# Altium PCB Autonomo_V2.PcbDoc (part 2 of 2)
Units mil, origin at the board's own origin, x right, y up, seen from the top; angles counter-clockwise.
Board outline 3937.01 x 3937.01 mil, 4 copper layers (Top Layer, GND, PWR, Bottom Layer), stack 62.204 mil thick; 148 components, 84 nets, 484 pads, 385 vias.
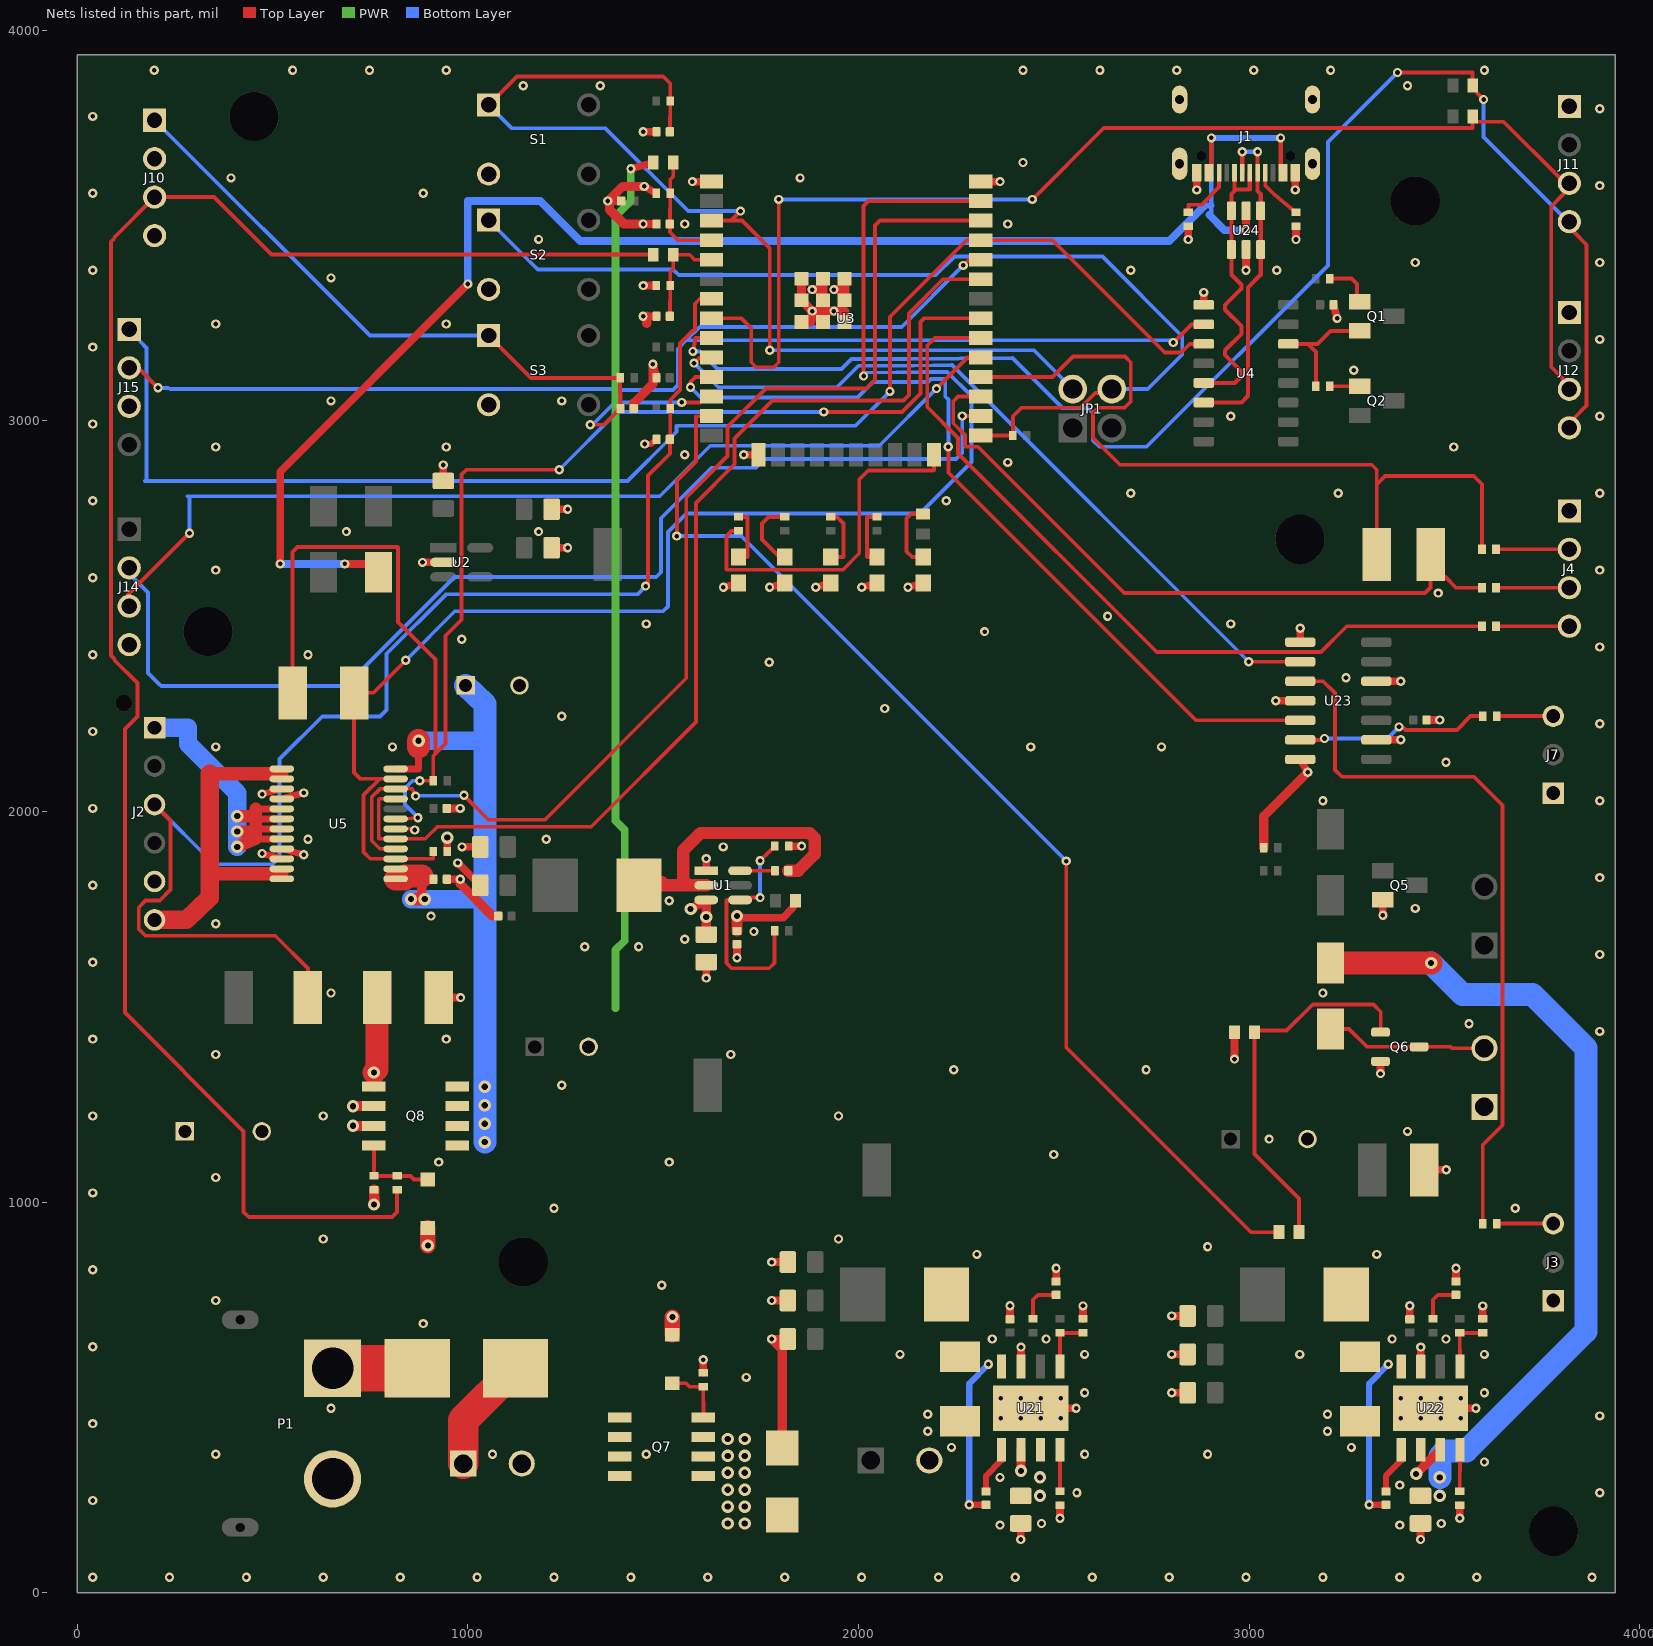
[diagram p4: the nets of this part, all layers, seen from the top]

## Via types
v1: diameter 23.62, hole 11.81, Top Layer to Bottom Layer, tented both sides, 334 vias
v2: diameter 31.5, hole 15.75, Top Layer to Bottom Layer, tented both sides, 51 vias

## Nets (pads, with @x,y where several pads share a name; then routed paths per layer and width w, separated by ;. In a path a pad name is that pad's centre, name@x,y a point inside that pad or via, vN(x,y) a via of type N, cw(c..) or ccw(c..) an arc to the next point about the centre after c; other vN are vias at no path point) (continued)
ENC_B: C18.1 J2.3 R15.2 TP4.1 U3.7 | length 3611.9
  Top Layer w9.84: J2.3@197.83,2017.72 239,1976.55 239,1800 211,1772 175,1772 157.48,1754.48 157.48,1699.61 175,1682.08 506.92,1682.08 590.55,1598.45 TP4.1@590.55,1523.62 ; v1(1455,2577) 1461,2583 1461,2860 1517.01,2916.01 C18.1@1517.01,2952.76 1518.21,2952.76 1518.21,2967.52 1517.91,2967.82 R15.2@1517.91,3031.5 1517.91,3053.91 1543,3079 1543,3198 1575,3230 1577,3230 1581,3234 1581,3300 1593.6,3312.6 U3.7@1624.02,3312.6
  Bottom Layer w9.84: J2.3@197.83,2017.72 350.55,1865 500,1865 518,1883 518,2134 627,2243 775,2243 792.04,2260.04 792.04,2403.77 944.27,2556 1434,2556 v1(1455,2577)
ESP_EN: C12.1 JP1.2 R6.2 S1.1 U3.3 | length 2674.4
  Top Layer w9.84: S1.1@1053.15,3809.06 1126.09,3882 1500,3882 1517.91,3864.09 R6.2@1517.91,3818.9 1517.91,3779.91 1517.01,3779 C12.1@1517.01,3740.16 ; U3.3@1624.02,3512.6 1673.6,3512.6 ; v1(1698,3537) 1673.6,3512.6 ; v1(1773,3181) 1773,3441.6 1702,3512.6 1673.6,3512.6
  Bottom Layer w9.84: S1.1@1053.15,3809.06 1113.21,3749 1352,3749 1564,3537 v1(1698,3537) ; v1(1773,3181) 2448.92,3181 JP1.2@2548.43,3081.5
ESP_RX: J15.2 U3.34 U4.2 | length 3704.7
  Top Layer w9.84: J15.2@161.42,3129.92 v1(206.69,3084.65) ; v1(2268,3398) 2282.6,3412.6 U3.34@2312.99,3412.6 ; v1(2806,3200.64) 2852.41,3247.05 U4.2@2883.86,3247.05
  Bottom Layer w9.84: v1(206.69,3084.65) 232.28,3084.65 ; 238.3,3082 1391,3082 1394,3079 1525,3079 1537.5,3091.5 1537.5,3184.78 1559.14,3206.41 ; v1(2268,3398) 2110.75,3240.75 1593.47,3240.75 1559.14,3206.41 ; v1(2806,3200.64) 2800.23,3206.41 1559.14,3206.41
ESP_TX: J15.1 U3.35 U4.3 | length 3574
  Top Layer w9.84: v1(2080.5,3075.5) 2080.5,3266.49 2276.6,3462.6 U3.35@2312.99,3462.6 2496.35,3462.6 2783.95,3175 2825.95,3175 2848,3197.05 U4.3@2883.86,3197.05
  Bottom Layer w9.84: 161.42,3202.76 177.17,3187.01 177.17,2850.39 ; 173.39,2845.9 1408.31,2845.9 1521.86,2959.45 1534.5,2972.09 1534.5,2987.64 1992.64,2987.64 v1(2080.5,3075.5)
ESTOP_G: J10.3 R42.2 R43.1 | length 4595.9
  Top Layer w9.84: 92.52,3464.57 86.61,3458.66 86.61,2399.61 94.49,2391.73 ; 96,2387 154,2329 154,2243 122,2211 122,1485 426,1181 426,975 439,962 805.9,962 818.9,975 R42.2@818.9,1031.3 ; 96,3471 J10.3@197.83,3572.83 350.17,3572.83 497,3426 1474.41,3426 R43.1@1474.41,3425.2
ESTOP_SENSE: C38.1 R43.2 R44.1 U3.5 | length 264.7
  Top Layer w9.84: C38.1@1517.01,3267.72 1517.01,3306 1517.91,3306.91 R44.1@1517.91,3346.46 1517.91,3381 1525.59,3388.68 R43.2@1525.59,3425.2 1568,3425.2 1580.6,3412.6 U3.5@1624.02,3412.6
EXP_IO4: J14.2 U3.26 | length 2819.4
  Top Layer w9.84: v1(2265.63,3012.6) U3.26@2312.99,3012.6
  Bottom Layer w9.84: 145.67,2596.46 181.1,2561.02 181.1,2354.33 210.63,2324.8 ; 215,2321 687,2321 966,2600 1482.14,2600 1494.64,2612.5 1494.64,2750.64 1624,2880 1738.21,2880 1760.45,2902.24 2250,2902.24 2265.63,2917.87 v1(2265.63,3012.6)
EXP_IO5: J14.3 U3.29 | length 2489.3
  Top Layer w9.84: 129.92,2555.12 v1(287.4,2712.6) ; v1(2199.59,3082.68) 2279.5,3162.6 U3.29@2312.99,3162.6
  Bottom Layer w9.84: 282.27,2806.98 1491.25,2806.98 1620.54,2936.27 2053.17,2936.27 v1(2199.59,3082.68) ; v1(287.4,2712.6) 287.4,2801.18
FB_SERVO: R23.2 R24.1 U22.5 | length 145.6
  Top Layer w9.84: U22.5@3539.57,578.74 3539.57,621 3539.37,621.2 R23.2@3539.37,665.16 R24.1@3598.43,665.16
FB_VJET: R19.2 R20.1 U21.5 | length 145.6
  Top Layer w9.84: U21.5@2515.94,578.74 2515.94,621 2515.75,621.2 R19.2@2515.75,665.16 R20.1@2574.8,665.16
GND: C1.N C2.2 C3.2 C4.2 C6.2 C7.2 C8.2 C9.2 C10.2 C11.2 C12.2 C13.2 C14.N C15.2 C16.2 C17.2 C18.2 C19.N C20.2 C21.N C22.2 C23.2 C24.2 C26.2 C27.2 C28.2 C29.2 C30.2 C31.2 C32.2 C34.2 C35.2 C36.2 C37.2 C38.2 D3.A D4.A D5.1 D6.1 D7.1 D8.1 D9.1 D12.A J1.A1_B12 J1.B1_A12 J1.SH1 J1.SH2 J1.SH3 J1.SH4 J2.5 J3.1 J4.1 J5.2 J7.1 J10.2 J10.4 J11.1 J12.1 J14.4 J15.3 P1.2 Q5.2 Q6.2 R2.2 R5.2 R8.2 R9.2 R12.2 R20.2 R21.2 R24.2 R25.2 R34.2 R36.2 R44.2 R45.2 S1.3 S2.3 S3.3 TP12.1 TP13.1 U1.1 U2.2 U3.1 U3.15 U3.38 U3.39 U4.1 U5.3 U5.4 U5.9 U5.10 U5.18 U21.7 U21.9 U22.7 U22.9 U23.1 U23.4 U23.7 U23.9 U23.12 U24.2 | length 4710.2
  Top Layer w9.84: U5.18@838.58,1955.71 850.39,1955.71 v1(864.17,1952.76)
  Top Layer w15.75: v1(1452.76,2940.94) 1468.5,2940.94 C18.2@1482.99,2952.76
  Top Layer w17.72: v1(473.11,1892.48) U5.10@523.62,1878.94 ; v1(473.11,2044.53) U5.3@523.62,2058.07 ; U5.9@523.62,1904.53 v1(579.84,1889.45) ; U5.4@523.62,2032.48 v1(579.84,2047.56)
  Top Layer w19.68: v1(883.7,2637.8) U2.2@936.99,2637.8 ; TP12.1@925.2,1523.62 v1(981.3,1523.62) ; C8.2@937.01,2846.26 v1(937.01,2887.2) ; C15.2@946.14,1826.77 v1(980.47,1826.77) ; C16.2@946.14,2007.87 v1(980.47,2007.87) ; R12.2@947.05,1897.64 v2(947.05,1933.15) ; v1(974.25,1868.46) C6.2@1031.69,1811.02 ; v1(984.84,1909.45) C7.2@1031.69,1909.45 ; C9.2@1214.37,2675.2 v1(1255.32,2675.2) ; C10.2@1214.37,2773.62 v1(1255.32,2773.62) ; v1(1358.11,3562.99) C11.2@1392.44,3562.99 ; v1(1448.66,3267.72) 1458.15,3267.72 C38.2@1482.99,3267.72 ; v1(1448.66,3503.94) C2.2@1482.99,3503.94 ; v1(1448.66,3740.16) C12.2@1482.99,3740.16 ; v1(1448.74,3346.46) R44.2@1482.09,3346.46 ; v1(1451.38,3600.39) R2.2@1482.09,3582.68 ; v1(1473.66,3145.08) C17.2@1482.99,3110.24 ; v1(1574.8,3612.6) U3.1@1624.02,3612.6 ; R45.2@1602.36,563.19 v1(1602.36,596.54) ; v1(1610.24,1573.43) C3.2@1610.24,1614.37 ; U1.1@1610.22,1848.43 v1(1610.24,1879.37) ; v1(1654.21,2574.29) D5.1@1692.91,2584.65 ; v1(1688.98,1625.83) C4.2@1688.98,1660.16 ; v1(1706.3,2913.39) U3.15@1743.7,2913.39 ; v1(1772.32,2574.29) D6.1@1811.02,2584.65 ; v1(1778.15,649.61) C22.2@1819.09,649.61 ; v1(1778.15,748.03) C23.2@1819.09,748.03 ; v1(1778.15,846.46) C28.2@1819.09,846.46 ; R5.2@1821.06,1911.42 v1(1854.41,1911.42) ; v1(1890.43,2574.29) D7.1@1929.13,2584.65 ; v1(2008.54,2574.29) D8.1@2047.24,2584.65 ; v1(2126.65,2574.29) D9.1@2165.35,2584.65 ; U3.38@2312.99,3612.6 v1(2362.2,3612.6) ; C27.2@2387.8,700.08 v1(2387.8,734.41) ; v1(2415.35,136.42) C24.2@2415.35,177.36 ; U21.7@2415.94,578.74 v1(2415.94,628.94) ; U21.9@2440.94,472.44 v1(2557.09,472.44) ; C26.2@2505.91,796.54 v1(2505.91,830.87) ; v1(2515.75,190.87) R21.2@2515.75,224.21 ; R20.2@2574.8,700.98 v1(2574.8,734.33) ; v1(2801.77,511.81) C31.2@2842.72,511.81 ; v1(2801.77,610.24) C29.2@2842.72,610.24 ; v1(2801.77,708.66) C30.2@2842.72,708.66 ; v1(2844.49,3464.49) R9.2@2844.49,3497.83 ; v1(2866.14,3591.34) J1.B1_A12@2866.14,3635.63 ; U4.1@2883.86,3297.05 v1(2883.86,3328.94) ; v1(2962.6,1366.14) R36.2@2962.6,1435.04 ; v1(2992.13,3385.83) U24.2@2992.13,3438.78 ; v1(3068.43,2283.46) U23.4@3130.91,2283.46 ; v1(3118.11,3591.34) J1.A1_B12@3118.11,3635.63 ; v1(3120.08,3464.49) R8.2@3120.08,3497.83 ; U23.7@3130.91,2133.46 v1(3149.88,2100.59) ; U23.1@3130.91,2433.46 v1(3130.91,2468.98) ; C13.2@3215.83,3297.24 v1(3225.16,3262.4) ; U23.9@3325.79,2183.46 v1(3388.27,2183.46) ; U23.12@3325.79,2333.46 v1(3388.27,2333.46) ; v1(3336.42,1328.94) Q6.2@3336.42,1360.24 ; v1(3342.52,1734.25) Q5.2@3342.52,1773.62 ; C35.2@3411.42,700.08 v1(3411.42,734.41) ; v1(3438.98,136.42) C32.2@3438.98,177.36 ; U22.7@3439.57,578.74 v1(3439.57,628.94) ; TP13.1@3448.82,1082.68 v1(3504.92,1082.68) ; C36.2@3454.02,2234.25 v1(3488.35,2234.25) ; U22.9@3464.57,472.44 v1(3580.71,472.44) ; C34.2@3529.53,796.54 v1(3529.53,830.87) ; v1(3539.37,190.87) R25.2@3539.37,224.21 ; R24.2@3598.43,700.98 v1(3598.43,734.33)
  Top Layer w23.62: v1(980.47,1826.77) 980.47,1814.81 1063,1732.28 C20.2@1077.48,1732.28 ; C37.2@1424.49,3031.5 1424.49,3045.49 1473.66,3094.66 v1(1473.66,3145.08) ; v1(1448.66,3503.94) 1399.67,3503.94 1362.5,3541.11 1362.5,3566.11 1396.79,3600.39 v1(1451.38,3600.39) ; 1458.15,3250 1458.15,3267.72 v1@1458.15,3268.54 ; v1(1778.15,649.61) 1805,622.76 D12.A@1805,370 ; U3.39@1854.33,3253.54 1878,3253.54 1878.61,3257.9 v1(1881.89,3281.1) ; U3.39@1854.33,3363.78 U3.39@1854.33,3308.66 v1(1881.89,3281.1) ; v1(1881.89,3336.22) 1908,3336.22 ; U3.39@1909.45,3253.54 v1(1881.89,3281.1) ; U3.39@1909.45,3308.66 1909.45,3335 1908.23,3336.22 1908,3336.22 ; U3.39@1909.45,3363.78 1909.45,3337.67 1908,3336.22 ; v1(1937.01,3336.22) 1963,3336.22 ; U3.39@1964.57,3253.54 1964.57,3280 1963.46,3281.1 v1(1937.01,3281.1) v1(1881.89,3281.1) ; U3.39@1964.57,3308.66 1964.57,3335 1963.35,3336.22 1963,3336.22 ; U3.39@1964.57,3363.78 1964.57,3337.79 1963,3336.22 ; R34.2@3037.2,1907.48 3037.2,1987.91 v1(3149.88,2100.59)
  other v1: 39.37,39.37 236.22,39.37 433.07,39.37 629.92,39.37 826.77,39.37 1023.62,39.37 1220.47,39.37 1417.32,39.37 1614.17,39.37 1811.02,39.37 2007.87,39.37 2204.72,39.37 2401.57,39.37 2598.43,39.37 2795.28,39.37 2992.13,39.37 3188.98,39.37 3385.83,39.37 3582.68,39.37 3877.95,39.37 2362.2,173.23 3385.83,173.23 2468.5,177.17 3492.13,177.17 39.37,236.22 2559.06,255.91 3897.64,255.91 3385.83,275.59 2362.2,295.28 3602.36,334.65 354.33,354.33 1062.99,354.33 1456.69,354.33 2578.74,354.33 2893.7,354.33 2238.19,372.05 3261.81,372.05 2177.17,413.39 3200.79,413.39 39.37,433.07 3897.64,452.76 2177.17,456.69 3200.79,456.69 649.61,472.44 2578.74,511.81 3602.36,511.81 1712.6,551.18 2106.3,610.24 2578.74,610.24 3129.92,610.24 3602.36,610.24 39.37,629.92 2342.52,649.61 2480.32,649.61 3366.14,649.61 3503.94,649.61 885.83,688.98 354.33,748.03 1496.06,787.4 39.37,826.77 2303.15,866.14 3326.77,866.14 2893.7,885.83 629.92,905.51 1948.82,905.51 1220.47,984.25 3681.1,984.25 39.37,1023.62 354.33,1062.99 925.2,1102.36 1515.75,1102.36 2500,1122.05 3051.18,1161.42 3405.51,1181.1 39.37,1220.47 629.92,1220.47 1948.82,1220.47 1240.16,1299.21 2244.09,1338.58 2736.22,1338.58 354.33,1377.95 1673.23,1377.95 39.37,1417.32 944.88,1417.32 3897.64,1437.01 3562.99,1456.69 649.61,1535.43 3188.98,1535.43 39.37,1614.17 3897.64,1633.86 1299.21,1653.54 1437.01,1653.54 1555.12,1673.23 1732.28,1692.91 354.33,1712.6 905.51,1732.28 3425.2,1751.97 1515.75,1771.65 39.37,1811.02 3897.64,1830.71 1653.54,1909.45 590.55,1929.13 1200.79,1929.13 39.37,2007.87 3188.98,2027.56 3897.64,2027.56 3503.94,2125.98 354.33,2165.35 807.09,2165.35 2440.94,2165.35 2775.59,2165.35 39.37,2204.72 3897.64,2224.41 1240.16,2244.09 2066.93,2263.78 3248.03,2342.52 1771.65,2381.89 39.37,2401.57 590.55,2401.57 3897.64,2421.26 984.25,2440.94 2322.83,2460.63 1456.69,2480.32 2952.76,2480.32 2637.8,2500 3484.25,2559.06 39.37,2598.43 354.33,2618.11 3897.64,2618.11 688.98,2716.54 1181.1,2716.54 39.37,2795.28 2224.41,2795.28 2696.85,2814.96 3228.35,2814.96 3897.64,2814.96 2381.89,2893.7 1555.12,2913.39 354.33,2933.07 944.88,2933.07 3523.62,2933.07 39.37,2992.13 2952.76,3011.81 3897.64,3011.81 649.61,3051.18 1240.16,3051.18 3267.72,3129.92 39.37,3188.98 3897.64,3208.66 354.33,3248.03 944.88,3248.03 649.61,3366.14 39.37,3385.83 2696.85,3385.83 3070.87,3385.83 3425.2,3405.51 3897.64,3405.51 1181.1,3464.57 1555.12,3503.94 2381.89,3503.94 39.37,3582.68 885.83,3582.68 3897.64,3602.36 393.7,3622.05 1850.39,3622.05 2421.26,3661.42 39.37,3779.53 3897.64,3799.21 1141.73,3858.27 1338.58,3858.27 3405.51,3858.27 196.85,3897.64 551.18,3897.64 748.03,3897.64 944.88,3897.64 2421.26,3897.64 2618.11,3897.64 2814.96,3897.64 3011.81,3897.64 3208.66,3897.64 3602.36,3897.64
I2C_SCL: J11.4 J12.4 R39.2 U3.9 | length 3749.8
  Top Layer w9.84: v1(1576,3178) 1583,3212.6 U3.9@1624.02,3212.6 ; v1(3380,3892) 3571.83,3892 R39.2@3572.83,3858.27 ; 3584.65,3838.58 v1(3600.39,3822.83) ; J12.4@3832.68,3007.87 3864.17,3039.37 3864.17,3450.79 3832.68,3482.28
  Bottom Layer w9.84: v1(1576,3178) 1594,3178 1639,3133 1956.54,3133 1982.42,3158.87 2123.18,3158.87 2394.19,3160.81 2522,3033 2587.5,3033 2600.69,3019.81 2600.69,2950 2616.93,2933.76 2737.76,2933.76 3202,3398 3202,3714 v1(3380,3892) ; v1(3600.39,3822.83) 3600.39,3726.38 3797.24,3529.53
I2C_SDA: J11.3 J12.3 R38.2 U3.8 | length 3346.3
  Top Layer w9.84: U3.8@1624.02,3262.6 1700.4,3262.6 1725.5,3237.5 1725.5,3150 1738,3137.5 1783.5,3137.5 1796,3150 v1(1796,3567) ; v1(2445,3567) 2628,3750 3571.83,3750 R38.2@3572.83,3779.53 ; R38.2@3584.65,3765.75 3651.57,3765.75 3793.31,3624.02 ; J12.3@3805.12,3106.3 3773.62,3137.8 3773.62,3549.21 3805.12,3580.71
  Bottom Layer w9.84: v1(1796,3567) v1(2445,3567)
IO0: JP1.4 R7.2 S2.1 U3.25 | length 2621.3
  Top Layer w9.84: U3.25@2312.99,2962.6 R7.2@2395.47,2962.6 2395.47,3012 2417.23,3033.76 2568.2,3033.76 2606,3071.56 2648.43,3071.56 JP1.4@2648.43,3081.5
  Bottom Layer w9.84: S2.1@1053.15,3513.78 1178.93,3388 1524.97,3388 1539.91,3373.06 2197.78,3373.06 2245.36,3420.64 2624.36,3420.64 2829,3216 2829,3170 2740.5,3081.5 JP1.4@2648.43,3081.5
J4_HB: J4.4 R40.1 | length 187.8
  Top Layer w9.84: R40.1@3632.09,2474.41 J4.4@3819.88,2474.41
J4_RX: J4.3 R18.1 | length 187.8
  Top Layer w9.84: R18.1@3632.09,2572.83 J4.3@3819.88,2572.83
J4_TX: J4.2 R17.1 | length 187.8
  Top Layer w9.84: R17.1@3632.09,2671.26 J4.2@3819.88,2671.26
JETSON_HB: R40.2 U3.30 | length 2033.5
  Top Layer w9.84: U3.30@2312.99,3212.6 2195.95,3212.6 2176.07,3192.72 2176.07,3035.35 2254.92,2956.51 2254.92,2916.6 2763.51,2408 3183.59,2408 3250,2474.41 R40.2@3596.26,2474.41
LED_3V3_A: D6.2 R29.2 | length 182.5
  Top Layer w9.84: D6.2@1811.02,2651.57 1798,2651.57 1753,2696.57 1753,2737.5 1769.63,2754.13 R29.2@1811.02,2754.13
LED_5V_A: D7.2 R30.2 | length 158
  Top Layer w9.84: D7.2@1929.13,2651.57 1961,2651.57 1962,2652.57 1962,2737.5 1945.37,2754.13 R30.2@1929.13,2754.13
LED_DATA_3V3: U3.11 U23.5 | length 2162.4
  Top Layer w9.84: v1(1570,3086) 1570,3100 1582.6,3112.6 U3.11@1624.02,3112.6 ; v1(2230,2934) 2230,2867.09 2863.63,2233.46 U23.5@3130.91,2233.46
  Bottom Layer w9.84: v1(1570,3086) 1596,3060 1997,3060 2037,3100 2178,3100 2185.66,3107.66 2221,3107.66 2222.22,3106.44 2222.22,3062.5 2230,3054.72 v1(2230,2934)
LED_DATA_5V: R27.1 U23.6 | length 493.9
  Top Layer w9.84: U23.6@3130.91,2183.46 v1@3190.46,2183.46 ; v1@3387,2222 3400,2209 3532,2209 3567.09,2244.09 R27.1@3598.23,2244.09
  Bottom Layer w9.84: v1(3192.91,2187.01) 3354.33,2187.01 v1(3383.86,2216.54)
LED_DIN: J7.3 R27.2 | length 144.5
  Top Layer w9.84: R27.2@3634.06,2244.09 J7.3@3778.54,2244.09
LED_HB: R28.1 U3.24 | length 909.4
  Top Layer w9.84: R28.1@1692.91,2718.31 1675,2718.31 1662,2705.31 1662,2620 1663,2619 1960,2619 2002,2661 2002,2850 2025,2873 2192.7,2873 2193.7,2874 U3.24@2193.7,2913.39
LED_HB_A: D5.2 R28.2 | length 147.6
  Top Layer w9.84: D5.2@1692.91,2651.57 1715,2651.57 1716,2652.57 1716,2753.13 1715,2754.13 R28.2@1692.91,2754.13
LED_SRV_A: D8.2 R31.2 | length 151.9
  Top Layer w9.84: D8.2@2047.24,2651.57 2023,2651.57 2022,2652.57 2022,2753.13 2023,2754.13 R31.2@2047.24,2754.13
LED_VJET_A: D9.2 R32.2 | length 179.4
  Top Layer w9.84: D9.2@2165.35,2651.57 2137.5,2651.57 2123.03,2666.04 2123.03,2749.84 2135,2761.81 R32.2@2165.35,2761.81
LIGHT_G: Q6.1 R35.2 R36.1 | length 974.7
  Top Layer w9.84: R35.2@3127.95,923.23 3127.95,1009 3013.78,1123.17 R36.1@3013.78,1435.04 3013.78,1439 3096,1439 3163,1506 3318.5,1506 3337,1487.5 3337,1435.04 Q6.1@3336.42,1435.04
LIGHT_N: D11.1 J9.2 Q6.3 | length 414
  Top Layer w9.84: D11.1@3208.66,1442.91 3256.09,1442.91 3301.36,1397.64 Q6.3@3435.24,1397.64 3516,1397.64 3519.74,1393.9 J9.2@3602.36,1393.9
LIGHTS: R35.1 U3.13 | length 2926.6
  Top Layer w9.84: v1(1535,2705) 1535,2847.34 1583.66,2896 1583.66,3011.26 U3.13@1624.02,3012.6 ; v1(2532,1873) 2532,1395.5 3004.5,923 3076.77,923 R35.1@3076.77,923.23
  Bottom Layer w9.84: v1(1535,2705) 1700,2705 v1(2532,1873)
MOT_A: J2.6 U5.1 U5.2 U5.11 U5.12 | length 850.8
  Top Layer w35.43: 338.58,1840.55 523.62,1840.55 ; 338.58,2096.46 523.62,2096.46
  Top Layer w47.24: J2.6@197.83,1722.44 279.53,1722.44 338.58,1779.53 338.58,1840.55 338.58,2096.46
MOT_B: J2.1 U5.5 U5.6 U5.7 U5.8 | length 933.5
  Top Layer w17.72: 456.69,1930.12 U5.8@523.62,1930.12 ; 456.69,1955.71 U5.7@523.62,1955.71 ; 456.69,1981.3 U5.6@523.62,1981.3 ; 456.69,2006.89 U5.5@523.62,2006.89
  Top Layer w31.5: v2(409.45,1909.45) 456.69,1930.12 456.69,1948.82 ; v2(409.45,1948.82) 456.69,1948.82 ; v2(409.45,1988.19) 456.69,1988.19 ; 456.69,2006.89 456.69,1988.19 ; 456.69,1948.82 456.69,1955.71 456.69,1981.3 456.69,1988.19
  Bottom Layer w47.24: J2.1@197.83,2214.57 283.46,2214.57 283.46,2173.23 409.45,2047.24 v2(409.45,1988.19) v2(409.45,1948.82) v2(409.45,1909.45)
MOT_IN1: U3.33 U5.17 U5.21 | length 2768.2
  Top Layer w9.84: U5.21@814.96,2032.48 773,2032.48 772,2031.48 772,1931.12 773,1930.12 799.8,1930.12 U5.17@814.96,1930.12 891,1930.12 921.88,1961 1316,1961 1584,2229 1584,2790 1683,2889 1683,2955 1780,3052 2115,3052 2129,3066 2129,3275 2216.6,3362.6 U3.33@2312.99,3362.6
MOT_IN2: U3.36 U5.16 U5.22 | length 2968.7
  Top Layer w9.84: U5.16@814.96,1904.53 774.47,1904.53 754,1925 754,2037.5 774.57,2058.07 U5.22@814.96,2058.07 857,2058.07 v1(866.14,2039.37) ; v1(990.16,2041.34) 1052.48,1979.02 1197.01,1979.02 1559,2341 1559,2804 1665,2910 1665,2985 1763,3083 2020,3083 2042,3105 2042,3500 2054.6,3512.6 U3.36@2312.99,3512.6
  Bottom Layer w9.84: v1(866.14,2039.37) v1(990.16,2041.34)
MOT_PWM: R12.1 TP2.1 U3.37 U5.15 U5.23 | length 3875.7
  Top Layer w9.84: U5.23@814.96,2083.66 774.33,2083.66 ; v1(841,2387) 758,2304 708.66,2304 TP2.1@708.66,2303.15 708.66,2100 725,2083.66 774.33,2083.66 ; R12.1@911.22,1897.64 911.22,1880 910.16,1878.94 U5.15@814.96,1878.94 750,1878.94 733,1895.94 733,2042.33 774.33,2083.66 ; v1(2013,3115) 2013,3550 2025.6,3562.6 U3.37@2312.99,3562.6
  Bottom Layer w9.84: v1(841,2387) 966.5,2512.5 1499.86,2512.5 1512.36,2525 1512.36,2715.36 1560,2763 2157,2763 2289,2895 2289,3063.44 2227.06,3125.38 2168.11,3125.38 2021.44,3123.44 v1(2013,3115)
MOT_STBY: R13.2 TP1.1 U3.31 U5.19 | length 3847.3
  Top Layer w9.84: TP1.1@551.18,2303.15 551.18,2664.18 564,2677 820,2677 821,2676 821,2485 917,2389 917,2147.78 ; U5.19@814.96,1981.3 846.46,1981.3 v1(872.05,1984.25) ; v1(877,2078.74) R13.2@911.22,2078.74 911.22,2142 917,2147.78 ; v1(1234,2875) 996.5,2875 984,2862.5 984,2491 943,2450 943,2173.78 917,2147.78 ; v1(1911,3023) 2111.3,3023 2158.36,3070.06 2158.36,3253.36 2167.6,3262.6 U3.31@2312.99,3262.6
  Bottom Layer w9.84: v1(872.05,1984.25) 838.58,2017.72 838.58,2059.06 858.27,2078.74 v1(877,2078.74) ; v1(1234,2875) 1382,3023 v1(1911,3023)
NetC25_1: C25.1 U21.1 | length 123.2
  Top Layer w15.75: C25.1@2326.77,259.13 2326.77,299.21 2365.94,338.58 U21.1@2365.94,366.14
NetC33_1: C33.1 U22.1 | length 123.2
  Top Layer w15.75: C33.1@3350.39,259.13 3350.39,299.21 3389.57,338.58 U22.1@3389.57,366.14
NetF1_1: F1.1 P1.1 | length 217
  Top Layer w118.11: P1.1@653.54,574.8 F1.1@870.56,574.8
NetF1_2: F1.2 P2.1 | length 299.3
  Top Layer w78.74: P2.1@987.99,330.71 987.99,440.94 F1.2@1121.56,574.8
NetJ1_A5: J1.A5 R8.1 | length 137.9
  Top Layer w9.84: J1.A5@3041.34,3635.63 3041.34,3602.36 3062.99,3580.71 R8.1@3120.08,3533.66
NetJ1_B5: J1.B5 R9.1 | length 154.2
  Top Layer w9.84: R9.1@2844.49,3533.66 2844.49,3553.15 2877.95,3553.15 2923.23,3598.43 J1.B5@2923.23,3635.63
NetJ3_3: J3.3 R16.1 | length 144.5
  Top Layer w9.84: R16.1@3634.06,944.88 J3.3@3778.54,944.88
NetQ1_1: Q1.1 R10.2 | length 127.7
  Top Layer w9.84: R10.2@3206.89,3364.17 3262.5,3364.17 3276,3350.67 3276,3305.12 Q1.1@3283.46,3305.12
NetQ2_1: Q2.1 R11.2 | length 76.6
  Top Layer w9.84: R11.2@3206.89,3088.58 Q2.1@3283.46,3088.58
Q7_G: D13.2 Q7.4 R45.1 | length 161
  Top Layer w9.84: D13.2@1523.62,536.42 1558,536.42 1567.06,527.36 R45.1@1602.36,527.36 1602.36,487.47 1602.83,487 Q7.4@1602.83,449.02
Q8_G: D14.2 Q8.4 R41.2 R42.1 | length 220.1
  Top Layer w9.84: Q8.4@759.37,1145.47 759.37,1106.47 759.84,1106 R41.2@759.84,1067.13 R42.1@818.9,1067.13 853,1067.13 862.06,1058.07 D14.2@897.64,1058.07
RC_SERVO: C34.1 R26.2 | length 113.3
  Top Layer w9.84: R26.2@3470.47,700.98 3470.47,750 3482.99,762.52 C34.1@3529.53,762.52
RC_VJET: C26.1 R22.2 | length 113.3
  Top Layer w9.84: R22.2@2446.85,700.98 2446.85,750 2459.37,762.52 C26.1@2505.91,762.52
RT_SERVO: R25.1 U22.4 | length 106.2
  Top Layer w9.84: R25.1@3539.37,260.04 3539.37,312 3539.57,312.2 U22.4@3539.57,366.14
RT_VJET: R21.1 U21.4 | length 106.2
  Top Layer w9.84: R21.1@2515.75,260.04 2515.75,312 2515.94,312.2 U21.4@2515.94,366.14
RTS: Q1.2 R11.1 U4.14 | length 314
  Top Layer w9.84: U4.14@3100.39,3197.05 3150,3197.05 ; R11.1@3171.06,3088.58 3171.06,3175.98 3150,3197.05 ; Q1.2@3283.46,3230.32 3208.27,3230.32 3175,3197.05 3150,3197.05
SERVO: R16.2 U23.3 | length 1856.8
  Top Layer w9.84: U23.3@3130.91,2333.46 3189.54,2333.46 3220,2303 3220,2106.5 3237.5,2089 3576,2089 3649,2016 3649,1196.77 3598.23,1146 R16.2@3598.23,944.88
SERVO_3V3: U3.10 U23.2 | length 1966.2
  Top Layer w9.84: v1(1579,3148) 1593.6,3162.6 U3.10@1624.02,3162.6 ; v1(2999.2,2383.46) U23.2@3130.91,2383.46
  Bottom Layer w9.84: v1(1579,3148) 1641,3086 1944.85,3086 2000,3141.15 2140.89,3141.15 2239.56,3143.1 v1(2999.2,2383.46)
START_BTN: C37.1 J10.1 R37.2 S3.1 U3.12 | length 1976.8
  Top Layer w9.84: S3.1@1053.15,3218.5 1161.42,3110.24 R37.2@1389.57,3110.24 1389.57,3070.91 1390.47,3070 C37.1@1390.47,3031.5 1377.95,3019.68 1348.43,2990.16 v1(1312.99,2990.16) ; v1(1547.24,3047.24) 1594.49,3047.24 U3.12@1624.02,3062.6
  Bottom Layer w9.84: J10.1@197.83,3769.69 749.02,3218.5 S3.1@1053.15,3218.5 ; v1(1312.99,2990.16) 1318.9,2990.16 1375.98,3047.24 v1(1547.24,3047.24)
SW: C5.2 L1.1 U1.2 | length 770.2
  Top Layer w31.5: L1.1@1437.99,1811.02 1437.99,1819 1496.06,1819 1496.06,1811.02 1564.98,1811.02 ; U1.2@1610.22,1811.02 1564.98,1811.02 ; C5.2@1820.16,1848.43 1845.43,1848.43 1887.88,1890.88 1887.88,1932.01 1875,1944.88 1595.88,1944.88 1551,1900 1551,1825 1564.98,1811.02
SW_SERVO: C33.2 D4.C L3.1 U22.8 | length 423.2
  Top Layer w15.75: v1(3307.09,225.12) C33.2@3350.39,225.12
  Bottom Layer w15.75: v1(3307.09,225.12) 3307.09,535.43 v1(3356.3,584.65)
SW_VJET: C25.2 D3.C L2.1 U21.8 | length 423.2
  Top Layer w15.75: v1(2283.46,225.12) C25.2@2326.77,225.12
  Bottom Layer w15.75: v1(2283.46,225.12) 2283.46,535.43 v1(2332.68,584.65)
UART2_RX: R18.2 TP6.1 U3.27 | length 1783.7
  Top Layer w9.84: U3.27@2312.99,3062.6 2255.14,3062.6 2242.54,3050 2242.54,2993.94 2272.64,2963.85 2272.64,2935 2273.64,2934 2305.25,2934 2680.25,2559 3450,2559 3464.57,2573.57 TP6.1@3464.57,2600 ; TP6.1@3464.57,2657.48 TP6.1@3464.57,2600 ; R18.2@3596.26,2572.83 3530,2572.83 3502.83,2600 TP6.1@3464.57,2600
UART2_TX: R17.2 TP5.1 U3.28 | length 2117
  Top Layer w9.84: U3.28@2312.99,3112.6 2496.6,3112.6 2549,3165 2682,3165 2697,3150 2697,3050 2680.76,3033.76 2612.5,3033.76 2600,3021.26 2600,2957 2669.22,2887.78 3313.99,2887.78 3326.77,2875 3326.77,2837.5 ; TP5.1@3326.77,2657.48 3326.77,2837.5 ; R17.2@3596.26,2671.26 3596.26,2837.74 3575,2859 3348.27,2859 3326.77,2837.5
USB_DN: J1.A7 J1.B7 U4.6 U24.3 U24.4 | length 854.6
  Top Layer w10.94: U4.6@2883.86,3047.05 2980.12,3047.05 2997.24,3064.17 2997.24,3341.73 3029.53,3374.02 U24.3@3029.53,3438.78 ; J1.A7@2982.28,3635.63 v1(2982.28,3688.98) ; v1(3021.65,3688.98) J1.B7@3021.65,3635.63 3021.65,3588.58 3029.53,3580.71 U24.4@3029.53,3537.6
  Top Layer w10.95: U24.3@3029.53,3438.78 U24.4@3029.53,3537.6
  Bottom Layer w10.94: v1(2982.28,3688.98) v1(3021.65,3688.98)
USB_DP: J1.A6 J1.B6 U4.5 U24.1 U24.6 | length 791.1
  Top Layer w10.94: U4.5@2883.86,3097.05 2963.19,3097.05 2980.32,3114.17 2980.32,3126.77 2938.19,3168.9 2938.19,3180.71 2980.32,3222.83 2980.32,3242.52 2938.19,3284.65 2938.19,3296.46 2980.32,3338.58 2980.32,3348.43 2954.72,3374.02 U24.1@2954.72,3438.78 ; U24.6@2954.72,3537.6 2954.72,3580.71 2962.6,3588.58 2962.6,3592.52 ; J1.B6@2962.6,3635.63 2962.6,3592.52 ; J1.A6@3001.97,3635.63 3001.97,3592.52 2962.6,3592.52
  Top Layer w10.95: U24.1@2954.72,3438.78 U24.6@2954.72,3537.6
VBAT: C1.P C3.1 C4.1 C24.1 C32.1 D11.2 D12.C D13.1 D14.1 J9.1 Q7.1 Q7.2 Q7.3 Q8.1 Q8.2 Q8.3 R1.1 R3.1 R41.1 TP7.1 U1.3 U21.2 U21.3 U22.2 U22.3 | length 5217.5
  Top Layer w19.68: v1(1417.32,3645.67) R1.1@1474.41,3661.42 ; v2@1700.79,1728.35 1807.09,1728.35 1830.71,1751.97 R3.1@1838.58,1771.65
  Top Layer w22.44: v2(1570.28,1750.55) U1.3@1610.22,1773.62
  Top Layer w23.62: C3.1@1610.24,1684.84 v2(1610.24,1729.72) U1.3@1610.22,1773.62 ; v2(2415.94,312.01) U21.2@2415.94,366.14 ; v2(3427.64,304.21) 3464.57,341.14 U22.3@3489.57,366.14
  Top Layer w25.59: v2(705.71,1195.47) Q8.3@759.37,1195.47 ; v2(705.71,1245.47) Q8.2@759.37,1245.47 ; Q8.1@759.37,1295.47 v2(759.37,1331.89)
  Top Layer w27.17: v2(759.84,994.02) R41.1@759.84,1031.3
  Top Layer w29.13: C4.1@1688.98,1694.17 v2(1688.98,1732.44)
  Top Layer w39.37: v2(897.64,888.7) D14.1@897.64,934.06 ; D13.1@1523.62,660.43 v2(1523.62,705.79)
  Top Layer w59.06: v2(759.37,1331.89) 767.72,1340.24 TP7.1@767.72,1523.62 ; D11.2@3208.66,1612.2 3208.66,1612 v2(3466,1612)
  PWR w19.68: 1377.95,1496.06 1377.95,1645.67 1401.57,1669.29 1401.57,1952.76 1377.95,1976.38 1377.95,3523.62 1417.32,3562.99 v1(1417.32,3645.67)
  Bottom Layer w59.06: v2(3466,1612) 3546,1532 3725,1532 3862,1395 3862,669 3556,363 3501.19,363 3488.19,350 v2(3488.19,295.28)
  other v2: 1665.35,177.17 1708.66,177.17 1665.35,220.47 1708.66,220.47 2464.57,248.03 3488.19,248.03 1665.35,263.78 1708.66,263.78 2464.57,295.28 1665.35,307.09 1708.66,307.09 1665.35,350.39 1708.66,350.39 1665.35,393.7 1708.66,393.7
VBAT_MOT: C14.P C15.1 Q8.5 Q8.6 Q8.7 Q8.8 U5.13 U5.14 U5.24 | length 1950.6
  Top Layer w17.72: U5.24@814.96,2109.25 874.02,2109.25 v2@874.02,2165.35
  Top Layer w19.68: 874.02,1840.55 879.92,1834.65 881.89,1832.68 887.8,1826.77 C15.1@912.13,1826.77
  Top Layer w23.62: v2@881.89,1775.59 881.89,1832.68 881.89,1834.65
  Top Layer w31.5: v2(854.33,1775.59) 881.89,1775.59 v2(889.76,1775.59)
  Top Layer w35.43: 814.96,1840.55 874.02,1840.55
  Top Layer w59.06: U5.13@814.96,1827.76 838,1827.76 838,1834.65 879.92,1834.65 881.89,1834.65 ; v2@874.02,2165.35 v2(874.02,2181.1)
  Bottom Layer w47.24: v2(854.33,1775.59) v2(889.76,1775.59) 1043.31,1775.59 ; v2(874.02,2181.1) 1043.31,2181.1
  Bottom Layer w59.06: C14.P@994.09,2322.83 1043.31,2275.59 1043.31,2181.1 1043.31,1775.59 v2(1043.31,1295.28) v2(1043.31,1248.03) v2(1043.31,1200.79) v2(1043.31,1153.54)
VBAT_SENSE: C2.1 R1.2 R2.1 U3.4 | length 297.4
  Top Layer w9.84: R1.2@1525.59,3661.42 1525.59,3625.68 1517.91,3618 R2.1@1517.91,3582.68 1517.91,3542.91 1517.01,3542 C2.1@1517.01,3503.94 1517.01,3483.09 1537.5,3462.6 U3.4@1624.02,3462.6
VBAT_SW: P2.2 Q7.5 Q7.6 Q7.7 Q7.8
VBST: C5.1 U1.6 | length 89.3
  Top Layer w9.84: U1.6@1696.86,1848.43 C5.1@1786.14,1848.43
VBUS: D2.1 J1.A4_B9 J1.B4_A9 U24.5 | length 4063.7
  Top Layer w11.81: J1.B4_A9@2903.54,3645.67 v1(2903.54,3724.41) ; J1.A4_B9@3080.71,3645.67 v1(3080.71,3724.41)
  Top Layer w19.68: v1(519.68,2633.86) 519.68,2870.08 v1(1000,3350.39) ; v1(685.04,2633.86) 736.22,2633.86 D2.1@771.65,2612.2 ; v1(2992.13,3488.19) U24.5@2992.13,3537.6
  Bottom Layer w11.81: 2897.64,3527.56 2903.54,3533.46 v1(2903.54,3724.41)
  Bottom Layer w15.75: 2885.83,3551.18 2903.54,3551.18 ; v1(2903.54,3724.41) v1(3080.71,3724.41)
  Bottom Layer w19.68: v1(519.68,2633.86) v1(685.04,2633.86) ; v1(1000,3350.39) 1000,3562.99 1185.04,3562.99 1287.4,3460.63 2795.28,3460.63 2885.83,3551.18 ; 2897.64,3527.56 2937.01,3488.19 v1(2992.13,3488.19)
VFB: R4.2 R5.1 U1.4 | length 583.7
  Top Layer w9.84: U1.4@1696.86,1773.62 1663,1773.62 1662,1772.62 1662,1611.74 1675,1598.74 1771.47,1598.74 1785.24,1612.5 R4.2@1785.24,1694.88 ; U1.4@1724.41,1779.53 v1(1748.03,1779.53) ; v1(1748.03,1874.02) 1775.59,1901.57 R5.1@1785.24,1911.42
  Bottom Layer w9.84: v1(1748.03,1779.53) v1(1748.03,1874.02)
pads on no net: J1. J1.A8 J1.B8 J2. P1.SH1 P1.SH2 S1.2 S1.4 S2.2 S2.4 S3.2 S3.4 U2.4 U3.14 U3.17 U3.18 U3.19 U3.20 U3.21 U3.22 U3.23 U3.32 U4.7 U4.8 U4.9 U4.10 U4.11 U4.12 U4.15 U23.8 U23.11

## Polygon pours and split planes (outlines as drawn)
GND on Top Layer "GND_TOP" (solid, remove dead copper, pour order 18): 15.75,15.75 3921.26,15.75 3921.26,3921.26 15.75,3921.26
GND on Top Layer "T_GND_D4" (solid, remove dead copper, pour order 11): 3173.23,322.83 3385.83,322.83 3385.83,478.35 3173.23,478.35
GND on Top Layer "T_GND_D3" (solid, remove dead copper, pour order 10): 2149.61,322.83 2362.2,322.83 2362.2,478.35 2149.61,478.35
SW_SERVO on Top Layer "T_SW_SERVO" (solid, remove dead copper, pour order 9): 3187.01,555.12 3401.38,555.12 3401.38,614.17 3334.65,614.17 3334.65,836.61 3187.01,836.61
SW_VJET on Top Layer "T_SW_VJET" (solid, remove dead copper, pour order 8): 2163.39,555.12 2377.76,555.12 2377.76,614.17 2311.02,614.17 2311.02,836.61 2163.39,836.61
VBAT_MOT on Top Layer "T_VBAT_MOT" (solid, remove dead copper, pour order 7): 940.94,1124.02 1070.87,1124.02 1070.87,1316.93 940.94,1316.93
+5V_SERVO on Top Layer "T_SERVO" (solid, remove dead copper, pour order 6): 2887.8,480.31 3102.36,480.31 3102.36,850.39 2887.8,850.39
+VJET on Top Layer "T_VJET" (solid, remove dead copper, pour order 5): 1864.17,299.21 2078.74,299.21 2078.74,877.95 1864.17,877.95
VBAT on Top Layer "T_VIN_SERVO" (solid, remove dead copper, pour order 4): 3409.45,224.41 3503.94,224.41 3503.94,346.46 3409.45,346.46
VBAT on Top Layer "T_VIN_VJET" (solid, remove dead copper, pour order 3): 2385.83,224.41 2480.32,224.41 2480.32,346.46 2385.83,346.46
VBAT on Top Layer "T_VBAT_Q7" (solid, remove dead copper, pour order 2): 1559.06,141.73 1862.2,141.73 1862.2,421.26 1559.06,421.26
VBAT_SW on Top Layer "T_VBAT_SW" (solid, remove dead copper, pour order 1): 1098.43,255.91 1425.2,255.91 1425.2,480.31 1098.43,480.31
+3V3 on PWR "L3_3V3" (solid, remove dead copper, pour order 17): 11.81,2464.57 3925.2,2464.57 3925.2,3925.2 11.81,3925.2
+5V on PWR "L3_5V_A" (solid, remove dead copper, pour order 14): 11.81,1559.06 1480.32,1559.06 1480.32,2440.94 11.81,2440.94
VBAT on PWR "L3_VBAT" (solid, remove dead copper, pour order 12): 11.81,11.81 3925.2,11.81 3925.2,1535.43 11.81,1535.43
+5V on PWR "L3_5V_C" (solid, remove dead copper, pour order 16): 1468.5,1885.83 1759.84,1885.83 1759.84,2440.94 1468.5,2440.94
+5V on PWR "L3_5V_B" (solid, remove dead copper, pour order 15): 1748.03,1559.06 3925.2,1559.06 3925.2,2440.94 1748.03,2440.94
VBAT on PWR "L3_VBAT_U1" (solid, remove dead copper, pour order 13): 1496.06,1496.06 1732.28,1496.06 1732.28,1870.08 1496.06,1870.08
GND on GND "GND_L2" (solid, remove dead copper, pour order 0): 11.81,11.81 3925.2,11.81 3925.2,3925.2 11.81,3925.2
GND on Bottom Layer "GND_BOT" (solid, remove dead copper, pour order 19): 15.75,15.75 3921.26,15.75 3921.26,3921.26 15.75,3921.26

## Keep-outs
Top Layer:
  lines w3.94: 167.32,2253.94 224.41,2253.94
Keep-Out Layer:
  circle w55.12: c3129.92,2696.85 r98.43
  circle w55.12: c334.65,2460.63 r98.43
  circle w55.12: c1141.73,846.46 r98.43
  circle w55.12: c3425.2,3562.99 r98.43
  circle w55.12: c452.76,3779.53 r98.43
  circle w55.12: c3779.53,157.48 r98.43
  rectangle: 1614.17,3901.57 2322.83,3937.01
  rectangle: 2330.71,3645.67 2381.89,3937.01
  rectangle: 1555.12,3645.67 1606.3,3937.01

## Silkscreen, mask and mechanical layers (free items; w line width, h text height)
Top Overlay:
  drawing of 1671 lines, arcs and shapes, not listed
  text "GND" at 3674.06,3772.99 h31.5 r90
  text "START" at 319.73,3718.11 h31.5 r90
  text "EN" at 918.5,3702.36 h51.18
  text "3V3" at 3673.8,3674.57 h31.5 r90
  text "GND" at 298.43,3640.17 h33.46
  text "SDA" at 3674.06,3576.14 h31.5 r90
  text "ESTOP" at 300.39,3559.53 h39.37
  text "SCL" at 3674.06,3477.72 h31.5 r90
  text "GND" at 300.39,3461.1 h39.37
  text "USB" at 2817.72,3445.1 h51.18
  text "BOOT" at 848.82,3407.7 h51.18
  text "START / PARO EMERG." at 687.4,3312.17 h51.18 r90
  text "GND" at 3674.06,3245.43 h31.5 r90
  text "TX0" at 234.25,3220.55 h39.37
  text "SENSORES I2C" at 3605.47,3214.61 h51.18 r90
  text "AUTO-RESET" at 2432.68,3213.21 h51.18
  text "3V3" at 3673.8,3147.01 h31.5 r90
  text "EN" at 2520.47,3141.73 h39.37
  text "IO0" at 2615.75,3142.21 h39.37
  text "RX0" at 234.25,3122.13 h39.37
  text "START" at 814.17,3112.43 h51.18
  text "SDA" at 3674.06,3048.58 h31.5 r90
  text "GND" at 234.25,3023.7 h39.37
  text "SCL" at 3674.06,2950.16 h31.5 r90
  text "3V3" at 234.25,2925.28 h39.37
  text "SERIAL/PROG ESP32" at 388.94,2820.83 h51.18 r90
  text "GPIO EXTRA" at 249.41,2761.72 h51.18
  text "GND" at 3597.64,2756.38 h39.37
  text "3V3" at 470.47,2726.46 h39.37
  text "TX" at 3676.04,2650 h31.5 r90
  text "IO4" at 470.47,2610.32 h39.37
  text "RX" at 3676.04,2551.57 h31.5 r90
  text "3V3" at 1321.65,2544.29 h47.24
  text "TX2" at 3290.16,2544.29 h47.24
  text "RX2" at 3427.95,2544.29 h47.24
  text "VJET" at 2111.81,2526.06 h39.37
  text "IO5" at 470.47,2511.89 h39.37
  text "HB" at 1704.32,2500.79 h39.37 r90
  text "5V" at 1944.48,2500.79 h39.37 r90
  text "3V3" at 1826.52,2475.59 h39.37 r90
  text "SRV" at 2063.06,2475.59 h39.37 r90
  text "HB" at 3676.04,2453.15 h31.5 r90
  text "GND" at 470.47,2413.47 h39.37
  text "SERIAL JETSON" at 3407.09,2390.16 h51.18 r90
  text "DIN" at 3513.78,2230.32 h39.37
  text "MOT B" at 300.39,2201.26 h39.37
  text "STBY" at 502.36,2189.96 h47.24
  text "PWM" at 672.05,2189.96 h47.24
  text "5V" at 3622.44,2132.36 h39.37
  text "3V3" at 300.39,2102.84 h39.37
  text "TIRA LED RGB" at 3242.05,2068.06 h51.18
  text "GND" at 3595.67,2033.94 h39.37
  text "ENC B" at 300.39,2012.25 h39.37
  text "ENC A" at 355.51,1894.14 h39.37
  text "GND" at 300.39,1807.56 h39.37
  text "BZ-" at 3514.63,1780.32 h31.5 r90
  text "PUENTE H MOTOR" at 413.78,1744.32 h51.18
  text "MOTOR + ENCODER" at 49.09,1726.77 h51.18 r90
  text "MOT A" at 300.39,1709.13 h39.37
  text "BUZZER" at 3271.65,1703.37 h51.18
  text "+5V" at 3431.5,1644.17 h39.37
  text "ENC_A" at 333.07,1635.51 h47.24
  text "ENC_B" at 510.24,1635.51 h47.24
  text "Alain Iribe Haddad" at 2222.87,1459.45 h78.74
  text "VBAT" at 718.9,1410.43 h47.24
  text "GND" at 888.58,1410.43 h47.24
  text "RoboUAQ 2026  -  PCB v2" at 2231.77,1403.23 h55.12
  text "LUZ-" at 3307.09,1380.79 h39.37
  text "LUCES" at 3251.18,1293.92 h51.18
  text "VBAT" at 3404.72,1230.32 h39.37
  text "VJET" at 1983.07,1188.76 h47.24
  text "5V" at 1589.76,1186.02 h47.24
  text "5V_SRV" at 3241.73,969.49 h47.24
  text "GND" at 3412.2,969.49 h47.24
  text "PWM" at 3501.18,931.1 h39.37
  text "SERVO 5V" at 3354.72,847.07 h51.18
  text "5V" at 3622.44,833.15 h39.37
  text "ALIM. JETSON 10V" at 2291.14,829.87 h51.18
  text "BATERIA" at 303.54,822.83 h51.18
  text "GND" at 3595.67,734.73 h39.37
  text "+" at 736.22,584.72 h62.99
  text "SWITCH" at 770.08,429.75 h51.18
  text "+10V" at 1984.25,429.61 h39.37
  text "GND" at 2179.18,426.38 h31.5 r90
  text "IN" at 967.72,421.26 h39.37
  text "OUT" at 1098.03,417.8 h39.37
  text "-" at 740.16,258.51 h62.99
Mechanical 1:
  the board outline again, w3.94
